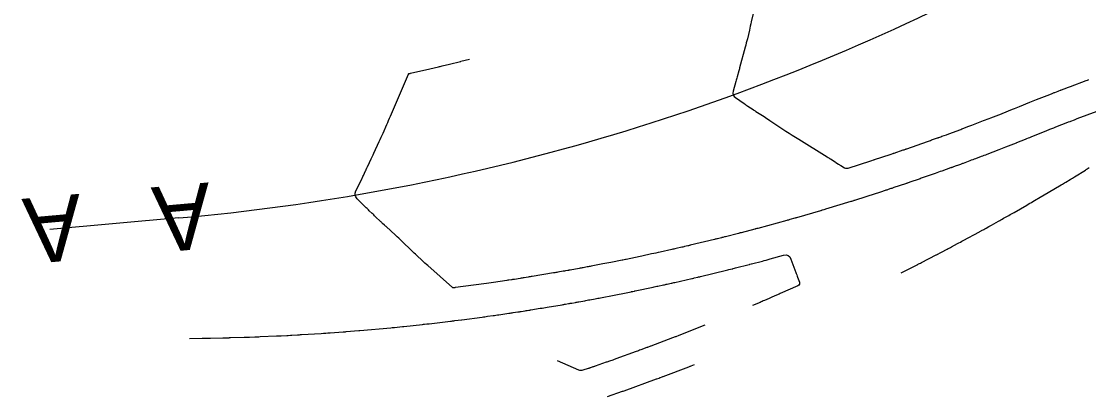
# Model space of a CAD drawing. Extents: x 688474 to 694748, y 765018 to 767373.
# Drawn here: x 688651.5 to 688749.1, y 766923.1 to 766957.4 of the extents above; entities that cross this region are included whole.
import ezdxf

# ---------------------------------------------------------------- set-up
doc = ezdxf.new("R2010")
doc.units = 0
for name, color, linetype in [('Prop_Contours_Major', 7, 'Continuous'), ('Prop_Contours_Minor', 7, 'Continuous'), ('R_Horz Alg', 7, 'Continuous')]:
    doc.layers.add(name, color=color, linetype=linetype)

msp = doc.modelspace()

# ---------------------------------------------------------------- linework, layer by layer
at = {"layer": 'Prop_Contours_Major'}
for points in [[(688666.896, 766928.458), (688668.039, 766928.477), (688668.23, 766928.48), (688668.42, 766928.483), (688668.611, 766928.486), (688668.801, 766928.489), (688669.941, 766928.508), (688669.972, 766928.508), (688670.003, 766928.509), (688670.033, 766928.509), (688670.064, 766928.51), (688670.217, 766928.514), (688670.309, 766928.516), (688670.474, 766928.52), (688670.512, 766928.521), (688670.55, 766928.522), (688670.587, 766928.524), (688670.625, 766928.525), (688671.873, 766928.566), (688671.997, 766928.57), (688672.121, 766928.574), (688672.245, 766928.578), (688672.37, 766928.582), (688672.866, 766928.598), (688672.991, 766928.602), (688673.115, 766928.606), (688673.239, 766928.611), (688673.363, 766928.617), (688674.856, 766928.685), (688674.955, 766928.689), (688675.055, 766928.694), (688675.154, 766928.698), (688675.254, 766928.702), (688675.78, 766928.726), (688675.816, 766928.727), (688675.851, 766928.729), (688675.886, 766928.731), (688675.921, 766928.733), (688676.132, 766928.744), (688676.217, 766928.748), (688676.253, 766928.75), (688676.762, 766928.781), (688676.851, 766928.786), (688676.94, 766928.792), (688677.029, 766928.797), (688677.118, 766928.802), (688678.934, 766928.913), (688679.139, 766928.926), (688679.344, 766928.939), (688679.548, 766928.953), (688679.753, 766928.968), (688680.936, 766929.054), (688681.024, 766929.06), (688681.112, 766929.066), (688681.155, 766929.07), (688681.199, 766929.073), (688682.377, 766929.167), (688682.451, 766929.173), (688682.476, 766929.175), (688685.303, 766929.431), (688685.412, 766929.441), (688685.52, 766929.451), (688685.548, 766929.453), (688685.575, 766929.456), (688685.602, 766929.459), (688685.629, 766929.461), (688686.357, 766929.534), (688686.449, 766929.543), (688686.483, 766929.547), (688688.188, 766929.73), (688688.288, 766929.741), (688688.389, 766929.752), (688688.589, 766929.773), (688688.639, 766929.779), (688688.689, 766929.784), (688688.739, 766929.79), (688688.789, 766929.796), (688690.748, 766930.031), (688690.849, 766930.044), (688690.951, 766930.056), (688691.052, 766930.068), (688691.153, 766930.08), (688691.754, 766930.153), (688691.804, 766930.159), (688693.637, 766930.407), (688693.764, 766930.424), (688693.892, 766930.441), (688694.02, 766930.459), (688694.147, 766930.476), (688694.657, 766930.545), (688694.785, 766930.563), (688694.912, 766930.581), (688695.04, 766930.599), (688695.167, 766930.618), (688696.105, 766930.756), (688696.2, 766930.77), (688696.295, 766930.784), (688696.39, 766930.799), (688696.485, 766930.813), (688696.902, 766930.875), (688696.979, 766930.886), (688697.056, 766930.898), (688697.134, 766930.91), (688697.211, 766930.922), (688697.586, 766930.98), (688697.673, 766930.993), (688697.76, 766931.007), (688697.933, 766931.034), (688697.976, 766931.041), (688698.02, 766931.048), (688698.063, 766931.055), (688698.106, 766931.062), (688698.966, 766931.205), (688699.124, 766931.231), (688699.282, 766931.257), (688699.439, 766931.283), (688699.597, 766931.31), (688700.98, 766931.538), (688701.052, 766931.55), (688701.123, 766931.562), (688701.195, 766931.574), (688701.267, 766931.587), (688701.553, 766931.638), (688701.625, 766931.65), (688701.697, 766931.663), (688701.768, 766931.676), (688701.84, 766931.688), (688702.18, 766931.748), (688702.261, 766931.762), (688702.341, 766931.777), (688702.422, 766931.791), (688702.502, 766931.806), (688703.029, 766931.902), (688703.144, 766931.923), (688703.258, 766931.944), (688703.373, 766931.965), (688703.487, 766931.987), (688703.982, 766932.078), (688704.102, 766932.1), (688704.223, 766932.123), (688704.343, 766932.146), (688704.463, 766932.169), (688705.713, 766932.415), (688705.873, 766932.446), (688706.033, 766932.478), (688706.194, 766932.509), (688706.354, 766932.541), (688707.289, 766932.724), (688707.317, 766932.729), (688707.345, 766932.735), (688707.443, 766932.755), (688707.567, 766932.78), (688707.59, 766932.785), (688707.612, 766932.79), (688707.635, 766932.794), (688707.658, 766932.799), (688709.278, 766933.143), (688709.39, 766933.167), (688709.503, 766933.191), (688709.616, 766933.215), (688709.729, 766933.239), (688710.233, 766933.346), (688710.319, 766933.364), (688710.406, 766933.383), (688710.492, 766933.402), (688710.578, 766933.421), (688710.923, 766933.498), (688711.009, 766933.518), (688711.095, 766933.537), (688711.182, 766933.557), (688711.268, 766933.576), (688712.831, 766933.929), (688712.867, 766933.937), (688712.902, 766933.945), (688713.01, 766933.97), (688713.045, 766933.979), (688713.368, 766934.054), (688713.428, 766934.068), (688713.488, 766934.082), (688713.547, 766934.096), (688713.607, 766934.111), (688715.992, 766934.69), (688716.106, 766934.717), (688716.22, 766934.745), (688716.512, 766934.816), (688716.537, 766934.822), (688716.563, 766934.828), (688716.588, 766934.834), (688716.613, 766934.84), (688716.739, 766934.872), (688716.814, 766934.891), (688718.065, 766935.21), (688718.101, 766935.219), (688718.136, 766935.228), (688718.241, 766935.256), (688718.276, 766935.265), (688719.282, 766935.529), (688719.456, 766935.575), (688719.629, 766935.621), (688719.803, 766935.668), (688719.976, 766935.715), (688721.222, 766936.056), (688721.449, 766936.085), (688721.636, 766936.038), (688721.784, 766935.913), (688721.892, 766935.711), (688722.34, 766934.494), (688722.381, 766934.382), (688722.421, 766934.27), (688722.462, 766934.158), (688722.501, 766934.046), (688722.659, 766933.596), (688722.68, 766933.492), (688722.664, 766933.403), (688722.611, 766933.33), (688722.521, 766933.274), (688720.904, 766932.549), (688720.82, 766932.511), (688720.735, 766932.473), (688720.65, 766932.436), (688720.565, 766932.399), (688720.139, 766932.214), (688719.884, 766932.102), (688719.46, 766931.918), (688719.361, 766931.875), (688719.262, 766931.832), (688719.163, 766931.79), (688719.064, 766931.747), (688718.373, 766931.453)], [(688714.013, 766929.652), (688711.944, 766928.835), (688711.871, 766928.807), (688711.798, 766928.778), (688711.725, 766928.75), (688711.652, 766928.723), (688711.36, 766928.612), (688711.287, 766928.584), (688711.214, 766928.556), (688711.141, 766928.529), (688711.068, 766928.501), (688709.085, 766927.747), (688709.058, 766927.736), (688708.975, 766927.705), (688708.832, 766927.652), (688708.805, 766927.642), (688708.778, 766927.632), (688708.751, 766927.622), (688708.723, 766927.612), (688708.154, 766927.406), (688708.05, 766927.369), (688707.946, 766927.331), (688707.842, 766927.294), (688707.738, 766927.256), (688705.887, 766926.584), (688705.812, 766926.557), (688705.737, 766926.53), (688705.661, 766926.504), (688705.586, 766926.477), (688705.285, 766926.372), (688705.209, 766926.346), (688705.134, 766926.32), (688705.058, 766926.293), (688704.983, 766926.267), (688703.987, 766925.919), (688703.934, 766925.9), (688703.881, 766925.882), (688703.827, 766925.863), (688703.774, 766925.845), (688703.56, 766925.773), (688703.506, 766925.754), (688703.453, 766925.736), (688703.399, 766925.718), (688703.346, 766925.7), (688702.871, 766925.537), (688702.774, 766925.514), (688702.678, 766925.508), (688702.583, 766925.521), (688702.488, 766925.553), (688700.539, 766926.397)]]:
    msp.add_lwpolyline(points, dxfattribs=at)
at = {"layer": 'Prop_Contours_Minor'}
for points in [[(688719.006, 766960.569), (688718.266, 766957.388), (688718.221, 766957.195), (688718.176, 766957.002), (688718.131, 766956.809), (688718.085, 766956.617), (688717.903, 766955.845), (688717.856, 766955.653), (688717.808, 766955.46), (688717.759, 766955.269), (688717.708, 766955.077), (688717.196, 766953.187), (688717.19, 766953.164), (688717.184, 766953.14), (688717.178, 766953.117), (688717.172, 766953.093), (688717.148, 766952.999), (688717.143, 766952.976), (688717.137, 766952.952), (688717.13, 766952.929), (688717.124, 766952.905), (688716.971, 766952.351), (688716.944, 766952.251), (688716.916, 766952.151), (688716.888, 766952.051), (688716.86, 766951.951), (688716.608, 766951.047), (688716.583, 766950.873), (688716.61, 766950.718), (688716.69, 766950.581), (688716.821, 766950.464), (688717.605, 766949.929), (688717.69, 766949.871), (688717.776, 766949.813), (688717.862, 766949.754), (688717.948, 766949.696), (688718.421, 766949.375), (688718.442, 766949.361), (688718.463, 766949.347), (688718.484, 766949.333), (688718.505, 766949.319), (688718.611, 766949.251), (688718.653, 766949.224), (688718.675, 766949.211), (688719.427, 766948.731), (688719.559, 766948.646), (688719.691, 766948.56), (688719.823, 766948.475), (688719.954, 766948.388), (688721.432, 766947.412), (688721.723, 766947.221), (688722.015, 766947.033), (688722.308, 766946.846), (688722.603, 766946.662), (688725.213, 766945.039), (688725.285, 766944.994), (688725.358, 766944.948), (688725.431, 766944.902), (688725.503, 766944.856), (688725.932, 766944.58), (688725.968, 766944.557), (688725.982, 766944.549), (688726.252, 766944.385), (688726.298, 766944.357), (688726.345, 766944.329), (688726.391, 766944.301), (688726.438, 766944.273), (688726.793, 766944.059), (688726.869, 766944.023), (688726.947, 766944.005), (688727.027, 766944.005), (688727.109, 766944.023), (688729.189, 766944.688), (688729.278, 766944.716), (688729.428, 766944.764), (688729.458, 766944.774), (688729.488, 766944.784), (688729.518, 766944.794), (688729.547, 766944.803), (688730.957, 766945.273), (688731.054, 766945.305), (688731.215, 766945.359), (688731.247, 766945.369), (688731.279, 766945.38), (688731.311, 766945.391), (688731.343, 766945.402), (688732.159, 766945.68), (688732.238, 766945.707), (688732.371, 766945.753), (688732.397, 766945.762), (688732.424, 766945.771), (688732.45, 766945.78), (688732.477, 766945.79), (688734.366, 766946.456), (688734.464, 766946.49), (688734.563, 766946.525), (688734.661, 766946.56), (688734.759, 766946.594), (688735.279, 766946.778), (688735.314, 766946.791), (688735.349, 766946.803), (688735.384, 766946.816), (688735.418, 766946.828), (688735.592, 766946.892), (688735.697, 766946.93), (688736.102, 766947.077), (688736.181, 766947.106), (688736.26, 766947.135), (688736.339, 766947.164), (688736.418, 766947.193), (688737.328, 766947.531), (688737.422, 766947.566), (688737.515, 766947.601), (688737.608, 766947.636), (688737.702, 766947.67), (688738.075, 766947.81), (688738.168, 766947.844), (688738.261, 766947.88), (688738.354, 766947.915), (688738.447, 766947.951), (688739.51, 766948.361), (688739.675, 766948.425), (688739.84, 766948.488), (688740.005, 766948.552), (688740.17, 766948.616), (688741.155, 766948.997), (688741.208, 766949.018), (688741.21, 766949.019), (688742.166, 766949.404), (688742.326, 766949.469), (688742.486, 766949.533), (688742.646, 766949.598), (688742.806, 766949.663), (688743.748, 766950.043), (688743.898, 766950.103), (688744.047, 766950.163), (688744.197, 766950.223), (688744.347, 766950.282), (688745.083, 766950.572), (688745.165, 766950.605), (688745.247, 766950.637), (688745.329, 766950.67), (688745.411, 766950.702), (688745.784, 766950.85), (688745.843, 766950.873), (688745.902, 766950.896), (688745.961, 766950.919), (688746.02, 766950.942), (688746.322, 766951.059), (688746.402, 766951.089), (688746.534, 766951.14), (688746.56, 766951.151), (688746.586, 766951.161), (688746.613, 766951.171), (688746.639, 766951.181), (688747.109, 766951.358), (688747.196, 766951.391), (688747.283, 766951.423), (688747.37, 766951.456), (688747.457, 766951.489), (688748.888, 766952.026), (688749.012, 766952.072), (688749.137, 766952.119)], [(688749.873, 766949.202), (688748.032, 766948.514), (688747.969, 766948.49), (688747.906, 766948.466), (688747.843, 766948.443), (688747.781, 766948.419), (688747.449, 766948.291), (688747.384, 766948.266), (688747.276, 766948.224), (688747.232, 766948.207), (688747.189, 766948.19), (688746.1, 766947.763), (688746.031, 766947.736), (688745.961, 766947.708), (688745.892, 766947.681), (688745.822, 766947.654), (688745.544, 766947.544), (688745.475, 766947.516), (688745.406, 766947.489), (688745.336, 766947.461), (688745.267, 766947.433), (688743.842, 766946.855), (688743.71, 766946.802), (688743.579, 766946.749), (688743.447, 766946.695), (688743.315, 766946.642), (688742.529, 766946.324), (688742.477, 766946.304), (688742.473, 766946.302), (688741.525, 766945.936), (688741.366, 766945.874), (688741.207, 766945.812), (688741.048, 766945.751), (688740.889, 766945.689), (688739.797, 766945.265), (688739.669, 766945.215), (688739.54, 766945.166), (688739.412, 766945.118), (688739.283, 766945.069), (688738.76, 766944.874), (688738.635, 766944.828), (688738.51, 766944.781), (688738.385, 766944.735), (688738.26, 766944.688), (688737.638, 766944.455), (688737.575, 766944.432), (688737.512, 766944.408), (688737.448, 766944.385), (688737.385, 766944.362), (688737.108, 766944.261), (688737.004, 766944.223), (688736.9, 766944.185), (688736.692, 766944.109), (688736.64, 766944.09), (688736.588, 766944.071), (688736.536, 766944.052), (688736.484, 766944.034), (688735.685, 766943.75), (688735.534, 766943.697), (688735.383, 766943.643), (688735.233, 766943.59), (688735.082, 766943.537), (688733.815, 766943.089), (688733.719, 766943.055), (688733.623, 766943.022), (688733.527, 766942.988), (688733.43, 766942.955), (688732.949, 766942.79), (688732.852, 766942.757), (688732.754, 766942.724), (688732.56, 766942.657), (688732.511, 766942.64), (688732.462, 766942.624), (688732.413, 766942.607), (688732.365, 766942.591), (688731.302, 766942.236), (688731.236, 766942.214), (688731.171, 766942.192), (688731.105, 766942.17), (688731.04, 766942.148), (688730.777, 766942.06), (688730.712, 766942.038), (688730.646, 766942.017), (688730.581, 766941.995), (688730.515, 766941.974), (688730.077, 766941.833), (688729.982, 766941.802), (688729.887, 766941.772), (688729.792, 766941.741), (688729.697, 766941.711), (688727.715, 766941.075), (688727.687, 766941.066), (688727.659, 766941.057), (688727.63, 766941.048), (688727.602, 766941.039), (688727.425, 766940.984), (688727.379, 766940.97), (688727.366, 766940.966), (688725.061, 766940.265), (688724.981, 766940.24), (688724.901, 766940.216), (688724.74, 766940.167), (688724.7, 766940.155), (688724.66, 766940.143), (688724.62, 766940.131), (688724.58, 766940.119), (688722.405, 766939.488), (688722.35, 766939.471), (688722.267, 766939.447), (688722.234, 766939.438), (688721.799, 766939.315), (688721.726, 766939.295), (688721.652, 766939.274), (688721.579, 766939.254), (688721.505, 766939.233), (688718.872, 766938.515), (688718.777, 766938.489), (688718.683, 766938.463), (688718.659, 766938.457), (688718.635, 766938.45), (688718.612, 766938.444), (688718.588, 766938.438), (688717.342, 766938.113), (688717.256, 766938.09), (688717.17, 766938.068), (688717.127, 766938.057), (688717.084, 766938.046), (688715.918, 766937.75), (688715.826, 766937.727), (688715.672, 766937.688), (688715.641, 766937.68), (688715.61, 766937.673), (688715.579, 766937.665), (688715.548, 766937.658), (688715.176, 766937.568), (688715.104, 766937.551), (688715.032, 766937.533), (688714.959, 766937.516), (688714.887, 766937.498), (688712.686, 766936.967), (688712.631, 766936.954), (688712.577, 766936.941), (688712.523, 766936.928), (688712.468, 766936.915), (688712.163, 766936.844), (688712.097, 766936.829), (688712.009, 766936.808), (688711.965, 766936.798), (688711.92, 766936.788), (688711.382, 766936.668), (688711.285, 766936.646), (688711.188, 766936.624), (688711.091, 766936.603), (688710.994, 766936.581), (688709.93, 766936.342), (688709.734, 766936.298), (688709.537, 766936.255), (688709.34, 766936.212), (688709.143, 766936.17), (688708.255, 766935.982), (688708.107, 766935.951), (688707.96, 766935.92), (688707.813, 766935.889), (688707.666, 766935.858), (688706.816, 766935.679), (688706.782, 766935.672), (688706.748, 766935.665), (688706.627, 766935.641), (688706.529, 766935.621), (688706.491, 766935.613), (688706.452, 766935.605), (688705.405, 766935.401), (688705.224, 766935.365), (688705.043, 766935.33), (688704.862, 766935.295), (688704.681, 766935.259), (688703.622, 766935.054), (688703.531, 766935.036), (688703.439, 766935.018), (688703.347, 766935.001), (688703.256, 766934.984), (688702.889, 766934.917), (688702.797, 766934.9), (688702.705, 766934.883), (688702.613, 766934.867), (688702.522, 766934.85), (688701.686, 766934.698), (688701.635, 766934.688), (688701.583, 766934.679), (688701.532, 766934.67), (688701.48, 766934.661), (688701.274, 766934.625), (688701.17, 766934.606), (688701.067, 766934.588), (688700.579, 766934.503), (688700.481, 766934.486), (688700.382, 766934.469), (688700.284, 766934.453), (688700.185, 766934.436), (688698.232, 766934.115), (688698.141, 766934.1), (688698.05, 766934.085), (688697.959, 766934.07), (688697.868, 766934.055), (688697.503, 766933.995), (688697.412, 766933.98), (688697.321, 766933.966), (688697.23, 766933.951), (688697.139, 766933.937), (688696.594, 766933.853), (688696.505, 766933.839), (688696.416, 766933.825), (688696.371, 766933.818), (688696.327, 766933.812), (688696.102, 766933.779), (688696.012, 766933.765), (688695.922, 766933.752), (688694.695, 766933.572), (688694.476, 766933.54), (688694.256, 766933.509), (688694.037, 766933.478), (688693.817, 766933.449), (688691.216, 766933.099), (688691.183, 766933.095), (688691.15, 766933.091), (688691.025, 766933.076), (688691.005, 766933.075), (688690.987, 766933.079), (688690.969, 766933.087), (688690.953, 766933.099), (688688.673, 766935.109), (688688.547, 766935.222), (688688.422, 766935.335), (688688.298, 766935.449), (688688.174, 766935.564), (688687.683, 766936.027), (688687.56, 766936.143), (688687.438, 766936.259), (688687.315, 766936.375), (688687.193, 766936.491), (688686.324, 766937.317), (688686.171, 766937.461), (688686.018, 766937.605), (688685.864, 766937.748), (688685.71, 766937.89), (688684.86, 766938.671), (688684.821, 766938.707), (688684.782, 766938.743), (688684.743, 766938.779), (688684.704, 766938.815), (688684.549, 766938.959), (688684.51, 766938.995), (688684.471, 766939.031), (688684.433, 766939.068), (688684.395, 766939.105), (688683.879, 766939.607), (688683.811, 766939.673), (688683.742, 766939.739), (688683.673, 766939.804), (688683.604, 766939.869), (688683.327, 766940.128), (688683.258, 766940.193), (688683.19, 766940.259), (688683.122, 766940.325), (688683.054, 766940.392), (688682.229, 766941.216), (688682.102, 766941.382), (688682.039, 766941.557), (688682.042, 766941.744), (688682.109, 766941.942), (688682.634, 766943.006), (688682.673, 766943.088), (688682.713, 766943.17), (688682.751, 766943.253), (688682.789, 766943.336), (688682.98, 766943.758), (688682.997, 766943.796), (688683.014, 766943.834), (688683.031, 766943.872), (688683.048, 766943.909), (688683.115, 766944.061), (688683.132, 766944.099), (688683.15, 766944.136), (688683.167, 766944.174), (688683.185, 766944.212), (688683.5, 766944.879), (688683.559, 766945.002), (688683.617, 766945.126), (688683.676, 766945.25), (688683.734, 766945.374), (688684.242, 766946.453), (688684.331, 766946.645), (688684.419, 766946.837), (688684.505, 766947.03), (688684.589, 766947.224), (688684.925, 766947.999), (688685.009, 766948.193), (688685.093, 766948.387), (688685.176, 766948.581), (688685.259, 766948.775), (688686.905, 766952.619), (688686.913, 766952.634), (688686.925, 766952.647), (688686.939, 766952.656), (688686.956, 766952.661), (688687.068, 766952.685), (688687.11, 766952.695), (688688.87, 766953.103), (688689.65, 766953.283), (688689.735, 766953.303), (688689.819, 766953.323), (688689.903, 766953.343), (688689.987, 766953.363), (688690.66, 766953.528), (688691.662, 766953.773), (688691.688, 766953.78), (688691.714, 766953.786), (688692.494, 766953.983)], [(688731.967, 766934.454), (688733.421, 766935.184), (688733.457, 766935.201), (688733.492, 766935.219), (688733.527, 766935.238), (688733.563, 766935.256), (688733.739, 766935.347), (688733.845, 766935.402), (688735.171, 766936.086), (688735.211, 766936.107), (688735.25, 766936.128), (688735.29, 766936.148), (688735.33, 766936.169), (688735.529, 766936.274), (688735.608, 766936.316), (688735.648, 766936.337), (688736.171, 766936.612), (688736.271, 766936.664), (688736.372, 766936.718), (688736.472, 766936.771), (688736.572, 766936.825), (688737.132, 766937.128), (688737.259, 766937.196), (688737.386, 766937.265), (688737.513, 766937.333), (688737.64, 766937.401), (688739.124, 766938.201), (688739.175, 766938.228), (688739.226, 766938.256), (688739.277, 766938.284), (688739.327, 766938.312), (688739.53, 766938.424), (688739.632, 766938.48), (688739.733, 766938.536), (688739.992, 766938.678), (688740.052, 766938.712), (688740.112, 766938.745), (688740.172, 766938.778), (688740.232, 766938.812), (688740.863, 766939.166), (688740.982, 766939.233), (688741.101, 766939.3), (688741.22, 766939.367), (688741.339, 766939.434), (688741.816, 766939.701), (688741.935, 766939.768), (688742.053, 766939.835), (688742.172, 766939.903), (688742.29, 766939.971), (688743.456, 766940.646), (688743.596, 766940.727), (688743.736, 766940.807), (688743.876, 766940.888), (688744.016, 766940.969), (688744.848, 766941.449), (688744.862, 766941.457), (688744.901, 766941.48), (688746.616, 766942.506), (688746.717, 766942.567), (688746.818, 766942.627), (688746.92, 766942.688), (688747.021, 766942.748), (688747.426, 766942.99), (688747.527, 766943.051), (688747.628, 766943.112), (688747.729, 766943.173), (688747.829, 766943.236), (688748.814, 766943.848), (688748.858, 766943.875), (688748.901, 766943.903), (688748.945, 766943.93), (688748.989, 766943.958), (688749.165, 766944.067)], [(688705.099, 766923.139), (688706.5, 766923.627), (688706.521, 766923.634), (688706.541, 766923.641), (688706.624, 766923.671), (688709.598, 766924.746), (688709.634, 766924.759), (688709.835, 766924.834), (688709.866, 766924.845), (688709.897, 766924.857), (688709.929, 766924.869), (688709.96, 766924.88), (688710.116, 766924.94), (688710.178, 766924.963), (688710.209, 766924.975), (688712.565, 766925.868), (688712.616, 766925.887), (688712.667, 766925.907), (688712.718, 766925.927), (688712.769, 766925.947), (688713.074, 766926.067)]]:
    msp.add_lwpolyline(points, dxfattribs=at)
at = {"layer": 'R_Horz Alg'}
msp.add_line((688665.92, 766939.464), (688654.098, 766938.419), dxfattribs=at)
for centre, radius, start, end in [((690143.23, 766296.111), 1476.39, 152.266532, 169.35), ((688648.306, 767138.687), 200, 275.05265, 296.92372)]:
    msp.add_arc(centre, radius, start, end, dxfattribs=at)

# ---------------------------------------------------------------- texts
for p in [(688668.644, 766942.717), (688656.822, 766941.672)]:
    msp.add_text('A', height=6, rotation=185.05265, dxfattribs=at).set_placement(p)

doc.saveas('drawing.dxf')
